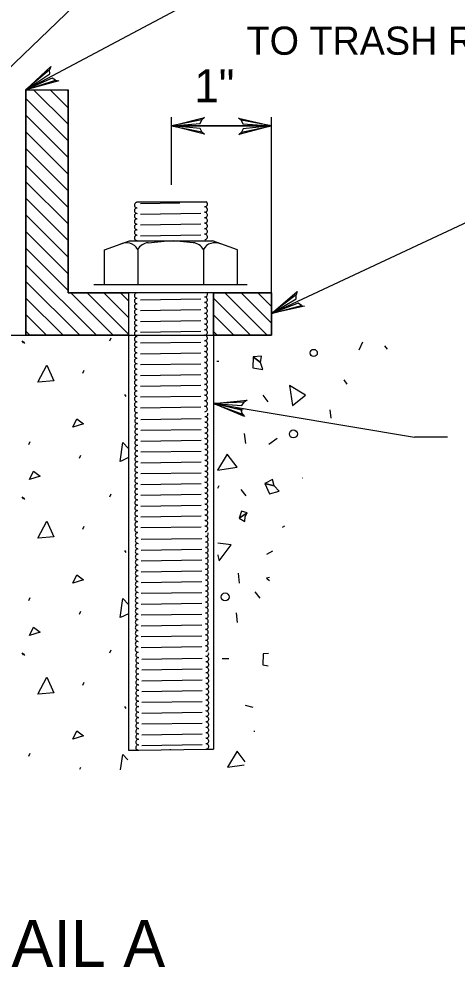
# Model space of a CAD drawing. Extents: x 636462 to 639890, y 299944 to 300538.
# Drawn here: x 639486.6 to 639533.2, y 300363.2 to 300464 of the extents above; entities that cross this region are included whole.
import ezdxf

# ---------------------------------------------------------------- set-up
doc = ezdxf.new("R2010")
doc.units = 0
doc.layers.add('Default', color=7, linetype='Continuous')

msp = doc.modelspace()

# ---------------------------------------------------------------- linework, layer by layer
at = {"layer": 'Default'}
for p, q in [((639483.19, 300456.49), (639505.64, 300478)), ((639487.37, 300456.49), (639505.58, 300466.19)), ((639487.37, 300456.49), (639491.87, 300456.49)), ((639487.37, 300456.49), (639487.37, 300430.39)), ((639491.87, 300452.81), (639488.19, 300456.49)), ((639491.87, 300454.57), (639489.95, 300456.49)), ((639491.87, 300456.34), (639491.72, 300456.49)), ((639491.87, 300434.89), (639491.87, 300456.49)), ((639491.87, 300451.04), (639487.37, 300455.54)), ((639491.87, 300449.27), (639487.37, 300453.77)), ((639502.85, 300446.38), (639502.85, 300453.57)), ((639513.48, 300434.89), (639513.48, 300453.57)), ((639513.48, 300452.63), (639502.85, 300452.63)), ((639502.85, 300452.63), (639513.48, 300452.63)), ((639513.48, 300452.63), (639507.17, 300452.63)), ((639491.87, 300447.51), (639487.37, 300452.01)), ((639491.87, 300445.74), (639487.37, 300450.24)), ((639491.87, 300443.97), (639487.37, 300448.48)), ((639491.87, 300442.21), (639487.37, 300446.71)), ((639491.87, 300440.44), (639487.37, 300444.94)), ((639499.18, 300444.58), (639506.52, 300444.58)), ((639499.55, 300444.39), (639503.74, 300444.45)), ((639513.48, 300432.68), (639539.63, 300444.96)), ((639491.87, 300438.67), (639487.37, 300443.18)), ((639499.55, 300443.26), (639505.96, 300443.36)), ((639499.55, 300442.11), (639505.96, 300442.21)), ((639491.87, 300436.91), (639487.37, 300441.41)), ((639495.73, 300439.45), (639498.37, 300440.43)), ((639498.37, 300440.43), (639507.22, 300440.43)), ((639499.55, 300440.96), (639505.96, 300441.06)), ((639500.36, 300440.21), (639502.42, 300440.43)), ((639505.15, 300440.21), (639503.09, 300440.43)), ((639509.86, 300439.45), (639507.22, 300440.43)), ((639491.87, 300435.14), (639487.37, 300439.64)), ((639495.73, 300435.72), (639495.73, 300439.45)), ((639499.26, 300439.5), (639499.26, 300435.78)), ((639506.25, 300439.5), (639506.25, 300435.78)), ((639509.86, 300435.72), (639509.86, 300439.45)), ((639494.86, 300430.39), (639487.37, 300437.88)), ((639493.1, 300430.39), (639487.37, 300436.11)), ((639494.58, 300435.78), (639510.88, 300435.78)), ((639491.33, 300430.39), (639487.37, 300434.34)), ((639513.48, 300434.89), (639491.87, 300434.89)), ((639496.63, 300430.39), (639492.13, 300434.89)), ((639498.28, 300430.5), (639493.89, 300434.89)), ((639498.28, 300432.27), (639495.66, 300434.89)), ((639498.28, 300434.03), (639497.43, 300434.89)), ((639498.28, 300434.89), (639498.28, 300386.27)), ((639499.55, 300434.16), (639505.96, 300434.25)), ((639507.3, 300434.89), (639507.3, 300386.38)), ((639511.23, 300430.39), (639507.3, 300434.32)), ((639513, 300430.39), (639508.5, 300434.89)), ((639513.48, 300431.67), (639510.26, 300434.89)), ((639513.48, 300433.44), (639512.03, 300434.89)), ((639513.48, 300430.39), (639513.48, 300434.89)), ((639499.55, 300433.01), (639505.96, 300433.11)), ((639489.56, 300430.39), (639487.37, 300432.58)), ((639509.47, 300430.39), (639507.3, 300432.55)), ((639499.55, 300431.86), (639505.96, 300431.96)), ((639474.92, 300430.39), (639513.48, 300430.39)), ((639487.8, 300430.39), (639487.37, 300430.81)), ((639496.3, 300429.79), (639496.44, 300430.11)), ((639499.55, 300430.71), (639505.96, 300430.81)), ((639507.7, 300430.39), (639507.3, 300430.79)), ((639486.93, 300429.79), (639487.07, 300429.57)), ((639487.07, 300429.71), (639487.21, 300429.49)), ((639499.55, 300429.56), (639505.96, 300429.66)), ((639523.13, 300429.63), (639522.74, 300428.79)), ((639525.5, 300429.26), (639525.77, 300428.89)), ((639499.55, 300428.41), (639505.96, 300428.51)), ((639499.55, 300427.26), (639505.96, 300427.36)), ((639507.67, 300427.62), (639507.88, 300427.62)), ((639493.42, 300426.34), (639493.57, 300426.66)), ((639499.55, 300426.11), (639505.96, 300426.21)), ((639499.55, 300424.96), (639505.96, 300425.06)), ((639521.16, 300425.63), (639521.49, 300425.19)), ((639497.86, 300424.07), (639498, 300423.86)), ((639512.57, 300424), (639513.08, 300423.32)), ((639499.55, 300423.82), (639505.96, 300423.91)), ((639507.3, 300423.14), (639528.67, 300419.56)), ((639499.55, 300422.67), (639505.96, 300422.76)), ((639509.61, 300422.65), (639510.44, 300422.45)), ((639519.66, 300422.47), (639519.77, 300421.56)), ((639499.59, 300421.43), (639506.01, 300421.52)), ((639499.59, 300420.28), (639506.01, 300420.37)), ((639487.67, 300418.78), (639487.82, 300419.1)), ((639499.59, 300419.13), (639506.01, 300419.22)), ((639510.58, 300419.92), (639510.7, 300418.89)), ((639514.07, 300419.4), (639513.19, 300418.76)), ((639532.17, 300419.56), (639528.67, 300419.56)), ((639499.59, 300417.98), (639506.01, 300418.07)), ((639493.07, 300417.32), (639493.21, 300417.64)), ((639499.59, 300416.83), (639506.01, 300416.92)), ((639499.59, 300415.68), (639506.01, 300415.77)), ((639516.75, 300415.23), (639516.76, 300415.23)), ((639499.59, 300414.53), (639506.01, 300414.63)), ((639507.86, 300414.36), (639507.74, 300414.09)), ((639510.23, 300414), (639510.74, 300413.31)), ((639486.93, 300413.21), (639487.07, 300412.99)), ((639487.07, 300413.13), (639487.21, 300412.91)), ((639496.3, 300413.21), (639496.44, 300413.53)), ((639499.59, 300413.38), (639506.01, 300413.48)), ((639499.59, 300412.23), (639506.01, 300412.33)), ((639499.59, 300411.08), (639506.01, 300411.18)), ((639493.42, 300409.76), (639493.57, 300410.08)), ((639499.59, 300409.93), (639506.01, 300410.03)), ((639514.64, 300409.99), (639514.88, 300410.12)), ((639499.64, 300408.69), (639506.06, 300408.79)), ((639509.2, 300408.09), (639507.77, 300408.29)), ((639497.86, 300407.49), (639498, 300407.27)), ((639499.64, 300407.54), (639506.06, 300407.64)), ((639507.77, 300407.04), (639507.77, 300407.03)), ((639507.77, 300407.03), (639507.77, 300407.02)), ((639507.77, 300407.03), (639507.77, 300407.03)), ((639507.77, 300407.02), (639507.77, 300407.01)), ((639507.77, 300407.02), (639507.77, 300407.02)), ((639507.77, 300407.02), (639507.77, 300407.02)), ((639507.77, 300407.01), (639507.77, 300407)), ((639507.77, 300407.01), (639507.77, 300407.01)), ((639507.77, 300407), (639507.77, 300406.99)), ((639507.77, 300407), (639507.77, 300407)), ((639507.77, 300407), (639507.77, 300407)), ((639507.77, 300406.99), (639507.77, 300406.98)), ((639507.77, 300406.99), (639507.77, 300406.99)), ((639507.77, 300406.98), (639507.77, 300406.98)), ((639507.77, 300406.98), (639507.77, 300406.98)), ((639512.99, 300407.12), (639513.61, 300407.47)), ((639499.64, 300406.39), (639506.06, 300406.49)), ((639499.64, 300405.24), (639506.06, 300405.34)), ((639509.93, 300405.08), (639510.05, 300404.04)), ((639499.64, 300404.09), (639506.06, 300404.19)), ((639499.64, 300402.95), (639506.06, 300403.04)), ((639511.71, 300403.12), (639512.22, 300402.44)), ((639487.67, 300402.2), (639487.82, 300402.52)), ((639499.64, 300401.8), (639506.06, 300401.89)), ((639493.07, 300400.74), (639493.21, 300401.06)), ((639509.73, 300400.89), (639509.84, 300399.85)), ((639499.64, 300400.65), (639506.06, 300400.74)), ((639499.64, 300399.5), (639506.06, 300399.59)), ((639499.64, 300398.35), (639506.06, 300398.44)), ((639496.3, 300396.62), (639496.44, 300396.94)), ((639499.64, 300397.2), (639506.06, 300397.3)), ((639486.93, 300396.62), (639487.07, 300396.41)), ((639487.07, 300396.54), (639487.21, 300396.33)), ((639499.69, 300395.96), (639506.1, 300396.05)), ((639508.22, 300396.01), (639508.94, 300396.03)), ((639499.69, 300394.81), (639506.1, 300394.91)), ((639499.69, 300393.66), (639506.1, 300393.76)), ((639493.42, 300393.18), (639493.57, 300393.5)), ((639499.69, 300392.51), (639506.1, 300392.61)), ((639497.86, 300390.9), (639498, 300390.69)), ((639499.69, 300391.36), (639506.1, 300391.46)), ((639510.67, 300391.05), (639511.5, 300390.86)), ((639499.69, 300390.21), (639506.1, 300390.31)), ((639499.69, 300389.06), (639506.1, 300389.16)), ((639499.69, 300387.91), (639506.1, 300388.01)), ((639511.64, 300388.33), (639511.65, 300388.23)), ((639499.69, 300386.76), (639506.1, 300386.86)), ((639487.67, 300385.62), (639487.82, 300385.94)), ((639498.28, 300386.27), (639499.36, 300386.27)), ((639499.36, 300386.27), (639506.54, 300386.38)), ((639502.66, 300386.33), (639502.78, 300386.33)), ((639506.54, 300386.38), (639507.3, 300386.38)), ((639493.11, 300384.26), (639493.21, 300384.48))]:
    msp.add_line(p, q, dxfattribs=at)
for points in [[(639490.51, 300457.49), (639490.86, 300457.42), (639487.37, 300456.49), (639490.51, 300457.49), (639490.16, 300457.72), (639487.37, 300456.49), (639489.9, 300458.18), (639489.88, 300458.6), (639487.37, 300456.49), (639490.01, 300458.95), (639489.88, 300458.6)], [(639494.7, 300434.89), (639498.28, 300434.89), (639498.28, 300430.39), (639487.37, 300430.39), (639487.37, 300456.49), (639491.87, 300456.49), (639491.87, 300434.89), (639494.7, 300434.89)], [(639506.08, 300452), (639506.35, 300451.77), (639502.85, 300452.63), (639506.08, 300452), (639505.88, 300452.37), (639502.85, 300452.63), (639505.88, 300452.89), (639506.06, 300453.27), (639502.85, 300452.63), (639506.34, 300453.52), (639506.06, 300453.27)], [(639510.24, 300453.24), (639509.97, 300453.46), (639513.48, 300452.63), (639510.24, 300453.24), (639510.44, 300452.87), (639513.48, 300452.63), (639510.45, 300452.34), (639510.28, 300451.97), (639513.48, 300452.63), (639510, 300451.71), (639510.28, 300451.97)], [(639513.48, 300430.39), (639507.3, 300430.39), (639507.3, 300434.89), (639511, 300434.89), (639513.48, 300434.89), (639513.48, 300430.39)], [(639516.66, 300433.54), (639517, 300433.46), (639513.48, 300432.68), (639516.66, 300433.54), (639516.32, 300433.79), (639513.48, 300432.68), (639516.08, 300434.26), (639516.08, 300434.67), (639513.48, 300432.68), (639516.22, 300435.03), (639516.08, 300434.67)], [(639488.63, 300425.38), (639489.59, 300427.19), (639490.34, 300425.52), (639488.67, 300425.38)], [(639510.39, 300422.01), (639510.62, 300421.74), (639507.3, 300423.14), (639510.39, 300422.01), (639510.26, 300422.41), (639507.3, 300423.14), (639510.33, 300422.92), (639510.57, 300423.27), (639507.3, 300423.14), (639510.89, 300423.47), (639510.57, 300423.27)], [(639492.37, 300420.61), (639492.79, 300421.5), (639493.5, 300420.96), (639492.37, 300420.61)], [(639497.39, 300416.96), (639497.67, 300418.99), (639498.28, 300418.35)], [(639498.28, 300417.37), (639497.42, 300416.97)], [(639487.75, 300415.05), (639488.17, 300415.94), (639488.88, 300415.41), (639487.75, 300415.05)], [(639488.63, 300408.8), (639489.59, 300410.61), (639490.34, 300408.94), (639488.67, 300408.8)], [(639507.77, 300406.98), (639507.92, 300406.4), (639509.2, 300408.09)], [(639492.37, 300404.03), (639492.79, 300404.91), (639493.5, 300404.38), (639492.37, 300404.03)], [(639513.25, 300404.63), (639512.93, 300404.55), (639513.25, 300404.31)], [(639497.39, 300400.37), (639497.67, 300402.4), (639498.28, 300401.77)], [(639498.28, 300400.78), (639497.42, 300400.39)], [(639487.75, 300398.47), (639488.17, 300399.36), (639488.88, 300398.83), (639487.75, 300398.47)], [(639513.14, 300396.54), (639512.58, 300396.51), (639512.56, 300395.33), (639513.12, 300395.24)], [(639488.63, 300392.22), (639489.59, 300394.03), (639490.34, 300392.36), (639488.67, 300392.22)], [(639492.37, 300387.44), (639492.79, 300388.33), (639493.5, 300387.8), (639492.37, 300387.44)], [(639497.44, 300384.19), (639497.67, 300385.82), (639498.21, 300385.26)], [(639510.66, 300385.05), (639509.82, 300386.16), (639508.8, 300384.46), (639510.56, 300384.71)]]:
    msp.add_lwpolyline(points, dxfattribs=at)
for points in [[(639512.29, 300427.49), (639511.52, 300428.1), (639511.5, 300426.93), (639512.56, 300426.75)], [(639511.52, 300428.1), (639512.29, 300427.49), (639512.42, 300428.15)], [(639515.69, 300422.93), (639517.09, 300424), (639515.38, 300425.03)], [(639509.83, 300416.35), (639508.76, 300417.75), (639507.74, 300416.05)], [(639512.78, 300414.62), (639513.76, 300414.37), (639513.57, 300415.04)], [(639513.76, 300414.37), (639512.78, 300414.62), (639513.27, 300413.52), (639514.3, 300413.82)], [(639510.04, 300410.93), (639510.88, 300411.49), (639510.3, 300411.68)], [(639510.88, 300411.49), (639510.04, 300410.93), (639510.65, 300410.59), (639510.66, 300411.11)]]:
    msp.add_lwpolyline(points, close=True, dxfattribs=at)
for centre, radius in [((639517.96, 300428.5), 0.383), ((639515.8, 300419.89), 0.423), ((639508.55, 300402.56), 0.423)]:
    msp.add_circle(centre, radius, dxfattribs=at)
for centre, radius, start, end in [((639499.19, 300444.21), 0.29, 94.4826, 274.9765), ((639506.38, 300444.33), 0.29, 274.4826, 60.9676), ((639499.19, 300443.63), 0.29, 94.4826, 274.9765), ((639499.19, 300443.63), 0.29, 94.4826, 274.9765), ((639499.19, 300443.05), 0.29, 94.4826, 274.9765), ((639499.19, 300443.05), 0.29, 94.4826, 274.9765), ((639506.38, 300443.75), 0.29, 274.4826, 94.9765), ((639506.38, 300443.74), 0.29, 274.4826, 94.9765), ((639506.38, 300443.17), 0.29, 274.4826, 94.9765), ((639506.38, 300443.16), 0.29, 274.4826, 94.9765), ((639499.19, 300442.48), 0.29, 94.4826, 274.9765), ((639499.19, 300442.47), 0.29, 94.4826, 274.9765), ((639499.19, 300441.9), 0.29, 94.4826, 274.9765), ((639499.19, 300441.89), 0.29, 94.4826, 274.9765), ((639506.38, 300442.59), 0.29, 274.4826, 94.9765), ((639506.38, 300442.58), 0.29, 274.4826, 94.9765), ((639506.38, 300442.01), 0.29, 274.4826, 94.9765), ((639506.38, 300442), 0.29, 274.4826, 94.9765), ((639499.19, 300441.32), 0.29, 94.4826, 274.9765), ((639506.38, 300441.42), 0.29, 274.4826, 94.9765), ((639506.38, 300440.84), 0.29, 274.4826, 94.9765), ((639498.04, 300438.82), 1.4, 29.4969, 119.7794), ((639499.19, 300440.74), 0.29, 94.4826, 274.9765), ((639500.47, 300438.82), 1.4, 94.7676, 150.5031), ((639505.03, 300438.82), 1.4, 29.4969, 85.2324), ((639507.46, 300438.82), 1.4, 65.2896, 150.5031), ((639499.19, 300434.6), 0.29, 94.4826, 274.9765), ((639499.19, 300434.02), 0.29, 94.4826, 274.9765), ((639506.38, 300434.16), 0.29, 274.4826, 94.9765), ((639506.38, 300434.74), 0.29, 274.4826, 18.2236), ((639499.19, 300433.44), 0.29, 94.4826, 274.9765), ((639499.19, 300432.86), 0.29, 94.4826, 274.9765), ((639506.38, 300433.58), 0.29, 274.4826, 94.9765), ((639506.38, 300433), 0.29, 274.4826, 94.9765), ((639499.19, 300432.28), 0.29, 94.4826, 274.9765), ((639506.38, 300432.42), 0.29, 274.4826, 94.9765), ((639506.38, 300431.84), 0.29, 274.4826, 94.9765), ((639499.19, 300431.7), 0.29, 94.4826, 274.9765), ((639499.19, 300431.13), 0.29, 94.4826, 274.9765), ((639506.38, 300431.26), 0.29, 274.4826, 94.9765), ((639499.19, 300430.55), 0.29, 94.4826, 274.9765), ((639499.19, 300429.97), 0.29, 94.4826, 274.9765), ((639506.38, 300430.68), 0.29, 274.4826, 94.9765), ((639506.38, 300430.09), 0.29, 274.4826, 94.9765), ((639499.19, 300429.39), 0.29, 94.4826, 274.9765), ((639499.19, 300428.81), 0.29, 94.4826, 274.9765), ((639506.38, 300429.51), 0.29, 274.4826, 94.9765), ((639506.38, 300428.93), 0.29, 274.4826, 94.9765), ((639499.19, 300428.23), 0.29, 94.4826, 274.9765), ((639506.38, 300428.35), 0.29, 274.4826, 94.9765), ((639506.38, 300427.77), 0.29, 274.4826, 94.9765), ((639499.19, 300427.65), 0.29, 94.4826, 274.9765), ((639499.19, 300427.07), 0.29, 94.4826, 274.9765), ((639506.38, 300427.19), 0.29, 274.4826, 94.9765), ((639499.19, 300426.49), 0.29, 94.4826, 274.9765), ((639499.19, 300425.92), 0.29, 94.4826, 274.9765), ((639506.38, 300426.61), 0.29, 274.4826, 94.9765), ((639506.38, 300426.03), 0.29, 274.4826, 94.9765), ((639499.19, 300425.34), 0.29, 94.4826, 274.9765), ((639499.19, 300424.76), 0.29, 94.4826, 274.9765), ((639506.38, 300425.45), 0.29, 274.4826, 94.9765), ((639506.38, 300424.87), 0.29, 274.4826, 94.9765), ((639499.19, 300424.18), 0.29, 94.4826, 274.9765), ((639506.38, 300424.29), 0.29, 274.4826, 94.9765), ((639506.38, 300423.71), 0.29, 274.4826, 94.9765), ((639499.19, 300423.6), 0.29, 94.4826, 274.9765), ((639499.19, 300423.02), 0.29, 94.4826, 274.9765), ((639506.38, 300423.12), 0.29, 274.4826, 94.9765), ((639499.19, 300422.44), 0.29, 94.4826, 274.9765), ((639499.24, 300421.86), 0.29, 94.4826, 274.9765), ((639506.38, 300422.54), 0.29, 274.4826, 94.9765), ((639506.42, 300422.01), 0.29, 274.4826, 18.2236), ((639499.24, 300421.29), 0.29, 94.4826, 274.9765), ((639499.24, 300420.71), 0.29, 94.4826, 274.9765), ((639506.42, 300421.43), 0.29, 274.4826, 94.9765), ((639506.42, 300420.85), 0.29, 274.4826, 94.9765), ((639499.24, 300420.13), 0.29, 94.4826, 274.9765), ((639506.42, 300420.27), 0.29, 274.4826, 94.9765), ((639506.42, 300419.68), 0.29, 274.4826, 94.9765), ((639499.24, 300419.55), 0.29, 94.4826, 274.9765), ((639499.24, 300418.97), 0.29, 94.4826, 274.9765), ((639506.42, 300419.1), 0.29, 274.4826, 94.9765), ((639499.24, 300418.39), 0.29, 94.4826, 274.9765), ((639499.24, 300417.81), 0.29, 94.4826, 274.9765), ((639506.42, 300418.52), 0.29, 274.4826, 94.9765), ((639506.42, 300417.94), 0.29, 274.4826, 94.9765), ((639499.24, 300417.23), 0.29, 94.4826, 274.9765), ((639499.24, 300416.66), 0.29, 94.4826, 274.9765), ((639506.42, 300417.36), 0.29, 274.4826, 94.9765), ((639506.42, 300416.78), 0.29, 274.4826, 94.9765), ((639499.24, 300416.08), 0.29, 94.4826, 274.9765), ((639506.42, 300416.2), 0.29, 274.4826, 94.9765), ((639506.42, 300415.62), 0.29, 274.4826, 94.9765), ((639499.24, 300415.5), 0.29, 94.4826, 274.9765), ((639499.24, 300414.92), 0.29, 94.4826, 274.9765), ((639506.42, 300415.04), 0.29, 274.4826, 94.9765), ((639499.24, 300414.34), 0.29, 94.4826, 274.9765), ((639499.24, 300413.76), 0.29, 94.4826, 274.9765), ((639506.42, 300414.46), 0.29, 274.4826, 94.9765), ((639506.42, 300413.88), 0.29, 274.4826, 94.9765), ((639499.24, 300413.18), 0.29, 94.4826, 274.9765), ((639499.24, 300412.6), 0.29, 94.4826, 274.9765), ((639506.42, 300413.3), 0.29, 274.4826, 94.9765), ((639506.42, 300412.71), 0.29, 274.4826, 94.9765), ((639499.24, 300412.03), 0.29, 94.4826, 274.9765), ((639506.42, 300412.13), 0.29, 274.4826, 94.9765), ((639499.24, 300411.45), 0.29, 94.4826, 274.9765), ((639499.24, 300410.87), 0.29, 94.4826, 274.9765), ((639506.42, 300411.55), 0.29, 274.4826, 94.9765), ((639506.42, 300410.97), 0.29, 274.4826, 94.9765), ((639499.24, 300410.29), 0.29, 94.4826, 274.9765), ((639499.24, 300409.71), 0.29, 94.4826, 274.9765), ((639506.42, 300410.39), 0.29, 274.4826, 94.9765), ((639506.42, 300409.81), 0.29, 274.4826, 94.9765), ((639499.29, 300409.13), 0.29, 94.4826, 274.9765), ((639506.47, 300408.69), 0.29, 274.4826, 94.9765), ((639506.47, 300409.27), 0.29, 274.4826, 18.2236), ((639499.29, 300408.55), 0.29, 94.4826, 274.9765), ((639499.29, 300407.97), 0.29, 94.4826, 274.9765), ((639506.47, 300408.11), 0.29, 274.4826, 94.9765), ((639499.29, 300407.39), 0.29, 94.4826, 274.9765), ((639499.29, 300406.82), 0.29, 94.4826, 274.9765), ((639506.47, 300407.53), 0.29, 274.4826, 94.9765), ((639506.47, 300406.95), 0.29, 274.4826, 94.9765), ((639499.29, 300406.24), 0.29, 94.4826, 274.9765), ((639499.29, 300405.66), 0.29, 94.4826, 274.9765), ((639506.47, 300406.37), 0.29, 274.4826, 94.9765), ((639506.47, 300405.79), 0.29, 274.4826, 94.9765), ((639499.29, 300405.08), 0.29, 94.4826, 274.9765), ((639506.47, 300405.21), 0.29, 274.4826, 94.9765), ((639506.47, 300404.63), 0.29, 274.4826, 94.9765), ((639499.29, 300404.5), 0.29, 94.4826, 274.9765), ((639499.29, 300403.92), 0.29, 94.4826, 274.9765), ((639506.47, 300404.05), 0.29, 274.4826, 94.9765), ((639499.29, 300403.34), 0.29, 94.4826, 274.9765), ((639499.29, 300402.76), 0.29, 94.4826, 274.9765), ((639506.47, 300403.47), 0.29, 274.4826, 94.9765), ((639506.47, 300402.89), 0.29, 274.4826, 94.9765), ((639499.29, 300402.19), 0.29, 94.4826, 274.9765), ((639499.29, 300401.61), 0.29, 94.4826, 274.9765), ((639506.47, 300402.3), 0.29, 274.4826, 94.9765), ((639506.47, 300401.72), 0.29, 274.4826, 94.9765), ((639499.29, 300401.03), 0.29, 94.4826, 274.9765), ((639506.47, 300401.14), 0.29, 274.4826, 94.9765), ((639506.47, 300400.56), 0.29, 274.4826, 94.9765), ((639499.29, 300400.45), 0.29, 94.4826, 274.9765), ((639499.29, 300399.87), 0.29, 94.4826, 274.9765), ((639506.47, 300399.98), 0.29, 274.4826, 94.9765), ((639499.29, 300399.29), 0.29, 94.4826, 274.9765), ((639499.29, 300398.71), 0.29, 94.4826, 274.9765), ((639506.47, 300399.4), 0.29, 274.4826, 94.9765), ((639506.47, 300398.82), 0.29, 274.4826, 94.9765), ((639499.29, 300398.13), 0.29, 94.4826, 274.9765), ((639499.29, 300397.56), 0.29, 94.4826, 274.9765), ((639506.47, 300398.24), 0.29, 274.4826, 94.9765), ((639506.47, 300397.66), 0.29, 274.4826, 94.9765), ((639499.29, 300396.98), 0.29, 94.4826, 274.9765), ((639506.47, 300397.08), 0.29, 274.4826, 94.9765), ((639499.34, 300396.4), 0.29, 94.4826, 274.9765), ((639499.34, 300395.82), 0.29, 94.4826, 274.9765), ((639506.52, 300395.96), 0.29, 274.4826, 94.9765), ((639506.52, 300396.54), 0.29, 274.4826, 18.2236), ((639499.34, 300395.24), 0.29, 94.4826, 274.9765), ((639499.34, 300394.66), 0.29, 94.4826, 274.9765), ((639506.52, 300395.38), 0.29, 274.4826, 94.9765), ((639506.52, 300394.8), 0.29, 274.4826, 94.9765), ((639499.34, 300394.08), 0.29, 94.4826, 274.9765), ((639499.34, 300393.5), 0.29, 94.4826, 274.9765), ((639506.52, 300394.22), 0.29, 274.4826, 94.9765), ((639506.52, 300393.64), 0.29, 274.4826, 94.9765), ((639499.34, 300392.93), 0.29, 94.4826, 274.9765), ((639506.52, 300393.06), 0.29, 274.4826, 94.9765), ((639506.52, 300392.48), 0.29, 274.4826, 94.9765), ((639499.34, 300392.35), 0.29, 94.4826, 274.9765), ((639499.34, 300391.77), 0.29, 94.4826, 274.9765), ((639506.52, 300391.89), 0.29, 274.4826, 94.9765), ((639499.34, 300391.19), 0.29, 94.4826, 274.9765), ((639499.34, 300390.61), 0.29, 94.4826, 274.9765), ((639506.52, 300391.31), 0.29, 274.4826, 94.9765), ((639506.52, 300390.73), 0.29, 274.4826, 94.9765), ((639499.34, 300390.03), 0.29, 94.4826, 274.9765), ((639499.34, 300389.45), 0.29, 94.4826, 274.9765), ((639506.52, 300390.15), 0.29, 274.4826, 94.9765), ((639506.52, 300389.57), 0.29, 274.4826, 94.9765), ((639499.34, 300388.87), 0.29, 94.4826, 274.9765), ((639506.52, 300388.99), 0.29, 274.4826, 94.9765), ((639506.52, 300388.41), 0.29, 274.4826, 94.9765), ((639499.34, 300388.29), 0.29, 94.4826, 274.9765), ((639499.34, 300387.72), 0.29, 94.4826, 274.9765), ((639506.52, 300387.83), 0.29, 274.4826, 94.9765), ((639499.34, 300387.14), 0.29, 94.4826, 274.9765), ((639499.34, 300386.56), 0.29, 94.4826, 274.9765), ((639506.52, 300387.25), 0.29, 274.4826, 94.9765), ((639506.52, 300386.67), 0.29, 274.4826, 94.9765)]:
    msp.add_arc(centre, radius, start, end, dxfattribs=at)

# ---------------------------------------------------------------- texts
for s, height, p in [('TO TRASH RACK FRAME', 2.998, (639510.83, 300460.2)), ('1"', 3.498, (639505.27, 300455.16)), ('DETAIL A', 4.997, (639472.47, 300363.22))]:
    msp.add_text(s, height=height, dxfattribs=at).set_placement(p)

doc.saveas('drawing.dxf')
